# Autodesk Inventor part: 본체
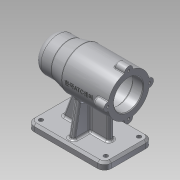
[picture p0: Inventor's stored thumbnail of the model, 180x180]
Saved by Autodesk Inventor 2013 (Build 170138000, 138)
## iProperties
Created: 2019-07
Part Number: 본체
Material: 알루미늄 6061
Document SubType Name: Modeling
Designer: Administrator
Density: 2.71 g/cm^3
Mass: 649.901 g
Surface Area: 669.553 cm^2
Volume: 239.816 cm^3
Author: Administrator
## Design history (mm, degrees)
sketch "스케치1"
  geometry: L1 (-56, 0)-(56, 0); L2 (56, 0)-(56, 21); L3 (56, 30)-(-11, 30); L4 (-11, 30)-(-31, 25); L5 (-31, 25)-(-56, 25); L6 (-56, 25)-(-56, 0); L7 (56, 21)-(41, 21); L8 (41, 21)-(41, 24); L9 (41, 24)-(-13, 24); L10 (-13, 24)-(-13, 21); L11 (-13, 21)-(-25, 21); L12 (-25, 21)-(-25, 17.5); L13 (-25, 17.5)-(-43, 17.5); L14 (-43, 17.5)-(-43, 16); L15 (-43, 16)-(-47, 16); L16 (-47, 16)-(-47, 10.5); L17 (-47, 10.5)-(-50, 10.5); L18 (-50, 10.5)-(-50, 0); L19 (56, 21)-(56, 30); 1 further point
  constraints: 38 end point, 9 horizontal, 9 vertical, 2 midpoint, 1 point on line
  dimensions: "d0" = 112 distance of L1.start L1.end; "d2" = 42 diameter of L7 L1; "d3" = 48 diameter of L9 L1; "d4" = 42 diameter of L11 L1; "d5" = 35 diameter of L13 L1; "d6" = 32 diameter of L15 L1; "d7" = 21 diameter of L17 L1; "d8" = 15 distance between parallel lines of L2 L8; "d9" = 54 distance between parallel lines of L10 L8; "d10" = 12 distance between parallel lines of L12 L10; "d11" = 18 distance between parallel lines of L14 L12; "d12" = 4 distance between parallel lines of L16 L14; "d13" = 3 distance between parallel lines of L16 L18; "d14" = 60 diameter of L3 L1; "d15" = 45 distance from line of L3.end L6; "d16" = 25 distance of L4.end L5.end; "d17" = 50 diameter of L5 L1
revolve "회전1" sketch "스케치1" stored, may be unused: angle "d18" = 90 deg
fillet "모깎기1" dims "d19" = 10, "d20" = 3, "d21" = 0.3
sketch "스케치2"
  geometry: C1 r 21 at (0, 0) reference; C2 r 6 at (0, 30)
  constraints: 1 centre point, 1 vertical alignment
  dimensions: "d22" = 30 distance of C1.centre C2.centre; "d23" = 12 diameter of C2
extrude "돌출1" join sketch "스케치2" distance "d24" = 16; taper "d25" = 0 deg
sketch "스케치3"
  geometry: A1 r 6 centre (0, 0) between (5.97, -0.6) and (-5.97, -0.6) reference; A2 r 6 centre (-30, -30) between (-29.4, -24.03) and (-29.4, -35.97) reference; A3 r 6 centre (0, -60) between (-5.97, -59.4) and (5.97, -59.4) reference; A4 r 6 centre (30, -30) between (29.4, -35.97) and (29.4, -24.03) reference; 4 further points
  constraints: 4 coincident
hole "구멍1" sketch "스케치3" at (0, 0), (-30, -30), (0, -60), (30, -30) diameter "d29" = 3.242; stored, may be unused: countersink angle "d33" = 90 deg, drill point angle "d35" = 118 deg; dims "d30" = 8, "d31" = 4, "d32" = 2, "d34" = 11
sketch "스케치4"
  geometry: L1 (-56, -70)-(56, -70); L2 (56, -70)-(56, -80); L3 (56, -80)-(-56, -80); L4 (-56, -80)-(-56, -70); 2 further points
  constraints: 8 end point, 2 parallel, 1 horizontal, 1 midpoint, 1 perpendicular, 1 vertical alignment
  dimensions: "d36" = 112 distance of L2.end L3.end; "d38" = 10 distance of L3.end L1.start; "d39" = 80 distance from line of L3 point (0, 0)
extrude "돌출2" join sketch "스케치4" stored distance "d40" = 70; taper "d41" = 0 deg
sketch "스케치5"
  geometry: L1 (0, 70)-(0, 0) reference; L2 (112, 0)-(112, 70) reference; L3 (20, 39)-(87, 39); L4 (87, 39)-(87, 31); L5 (87, 31)-(20, 31); L6 (20, 31)-(20, 39); 2 further points
  constraints: 8 end point, 2 parallel, 1 horizontal, 1 horizontal alignment, 1 midpoint, 1 perpendicular
  dimensions: "d42" = 20 distance between parallel lines of L1 L6; "d43" = 25 distance between parallel lines of L2 L4; "d44" = 8 distance of L5.end L3.start
extrude "돌출3" join sketch "스케치5" stored distance "d45" = 70; taper "d46" = 0 deg
feature "면 기울기1" dims angle "d47" = 20 deg
sketch "스케치6"
  geometry: L1 (-70, 35)-(-80, 35) reference; L2 (-70, -35)-(-70, 35) reference; L3 (-70, 28)-(-48.89, 24.278); 1 further point
  constraints: 2 end point, 1 point on line
  dimensions: "d48" = 7 distance from line of L3.start L1; "d49" = 100 deg angle of L2 L3
feature "리브1" sketch "스케치6" dims "d50" = 1, "d51" = 8, "d52" = 0, "d53" = 0, "d54" = 1, "d55" = 1
fillet "모깎기2" dims "d56" = 10
sketch "스케치7"
  geometry: A1 r 10 centre (92, -10) between (102, -10) and (92, 0) reference; A2 r 10 centre (0, -10) between (0, 0) and (-10, -10) reference; A3 r 10 centre (0, -60) between (-10, -60) and (0, -70) reference; 5 further points
  constraints: 3 coincident
hole "구멍2" sketch "스케치7" at (0, -10), (0, -60), (92, -58.141), (92, -10) diameter "d57" = 6; stored, may be unused: countersink angle "d61" = 90 deg, drill point angle "d63" = 118 deg; dims "d58" = 8, "d59" = 4, "d60" = 2, "d62" = 11
chamfer "모따기1" distance "d64" = 3; stored, may be unused: second distance "d65" = 2, angle "d66" = 45 deg
node "작업 평면1"
sketch "스케치8"
  geometry: L1 (33.5, -24)-(33.5, 24) reference; 2 further points
  constraints: 1 horizontal alignment, 1 other
  dimensions: "d67" = 42 distance from line of L1 point (-8.5, 0)
feature "엠보싱1" sketch "스케치8" dims "d0" = 112, "d2" = 42, "d3" = 48, "d4" = 42, "d5" = 35, "d6" = 32, "d7" = 21, "d8" = 15, "d9" = 54, "d10" = 12, "d11" = 18, "d12" = 4, "d13" = 3, "d14" = 60, "d15" = 45, "d16" = 25, "d17" = 50, "d68" = 0.5, "d69" = 0
fillet "모깎기4" dims "d72" = 3
fillet "모깎기5" dims "d73" = 1, "d74" = 3
chamfer "모따기2" distance "d75" = 1; stored, may be unused: second distance "d76" = 2, angle "d77" = 45 deg
node "솔리드1"
pattern_circular "원형 패턴1" dims angle "d27" = 360 deg
mirror "대칭1"
fillet "모깎기3" dims "d71" = 3
